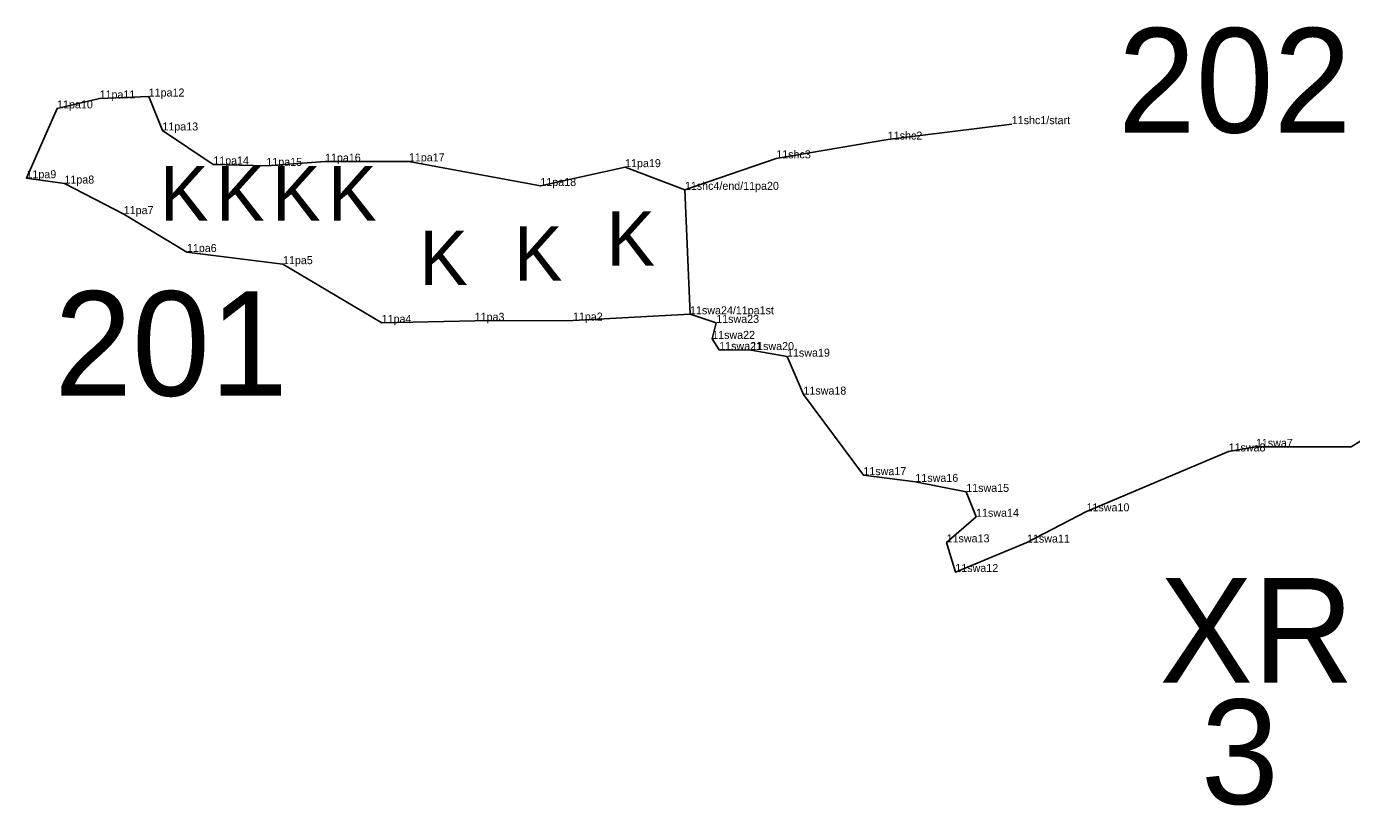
# Model space of a CAD drawing. Extents: x 2072529 to 2268812, y 436423 to 470008.
# Drawn here: x 2225567 to 2226395, y 447962 to 448449 of the extents above; entities that cross this region are included whole.
import ezdxf

# ---------------------------------------------------------------- set-up
doc = ezdxf.new("R2010")
doc.units = 0
for name, color, linetype in [('Old_Level_10', 7, 'Continuous'), ('Old_Level_20', 7, 'Continuous'), ('Old_Level_52', 7, 'Continuous'), ('Old_Level_55', 7, 'Continuous'), ('Old_Level_60', 7, 'Continuous'), ('Old_Level_62', 7, 'Continuous')]:
    doc.layers.add(name, color=color, linetype=linetype)

msp = doc.modelspace()

# ---------------------------------------------------------------- linework, layer by layer
at = {"layer": 'Old_Level_10'}
for points in [[(2225978.686, 448347.107), (2225981.906, 448269.333), (2225998.274, 448263.943), (2225995.753, 448253.963), (2226000.1, 448247.034), (2226020.097, 448246.98), (2226042.5, 448242.86), (2226052.746, 448219.139), (2226090.193, 448168.806), (2226122.677, 448164.597), (2226154.431, 448158.364), (2226160.56, 448142.804), (2226142.212, 448126.808), (2226147.631, 448108.287), (2226192.389, 448126.682), (2226229.566, 448146.2), (2226318.313, 448183.633), (2226335.372, 448186.476), (2226394.83, 448186.41), (2226419.056, 448201.541), (2226431.769, 448228.893), (2226430.927, 448298.983), (2226428.561, 448370.704), (2226419.335, 448414.909)], [(2226182.883, 448388.146), (2226105.414, 448378.517), (2226035.771, 448366.771), (2225978.686, 448347.107)]]:
    msp.add_lwpolyline(points, dxfattribs=at)
at = {"layer": 'Old_Level_20'}
for p, q in [((2225613.084, 448404.204), (2225613.084, 448404.204)), ((2225643.785, 448405.432), (2225643.785, 448405.432)), ((2225586.578, 448397.996), (2225586.578, 448397.996)), ((2226182.883, 448388.146), (2226182.883, 448388.146)), ((2225652.344, 448384.211), (2225652.344, 448384.211)), ((2226105.414, 448378.517), (2226105.414, 448378.517)), ((2225684.091, 448362.94), (2225684.091, 448362.94)), ((2225717.271, 448362.064), (2225717.271, 448362.064)), ((2225753.909, 448364.724), (2225753.909, 448364.724)), ((2225806.3, 448364.892), (2225806.3, 448364.892)), ((2225941.348, 448361.277), (2225941.348, 448361.277)), ((2226035.771, 448366.771), (2226035.771, 448366.771)), ((2225567.454, 448354.369), (2225567.454, 448354.369)), ((2225591.155, 448351.028), (2225591.155, 448351.028)), ((2225888.445, 448349.505), (2225888.445, 448349.505)), ((2225978.686, 448347.107), (2225978.686, 448347.107)), ((2225978.686, 448347.107), (2225978.686, 448347.107)), ((2225628.197, 448331.934), (2225628.197, 448331.934)), ((2225667.64, 448308.251), (2225667.64, 448308.251)), ((2225727.663, 448300.661), (2225727.663, 448300.661)), ((2225789.301, 448263.995), (2225789.301, 448263.995)), ((2225847.392, 448265.261), (2225847.392, 448265.261)), ((2225908.771, 448265.412), (2225908.771, 448265.412)), ((2225908.771, 448265.412), (2225908.771, 448265.412)), ((2225981.906, 448269.333), (2225981.906, 448269.333)), ((2225981.906, 448269.333), (2225981.906, 448269.333)), ((2225998.274, 448263.943), (2225998.274, 448263.943)), ((2225995.753, 448253.963), (2225995.753, 448253.963)), ((2226000.1, 448247.034), (2226000.1, 448247.034)), ((2226020.097, 448246.98), (2226020.097, 448246.98)), ((2226042.5, 448242.86), (2226042.5, 448242.86)), ((2226052.746, 448219.139), (2226052.746, 448219.139)), ((2226318.313, 448183.633), (2226318.313, 448183.633)), ((2226335.372, 448186.476), (2226335.372, 448186.476)), ((2226394.83, 448186.41), (2226394.83, 448186.41)), ((2226090.193, 448168.806), (2226090.193, 448168.806)), ((2226122.677, 448164.597), (2226122.677, 448164.597)), ((2226154.431, 448158.364), (2226154.431, 448158.364)), ((2226229.566, 448146.2), (2226229.566, 448146.2)), ((2226160.56, 448142.804), (2226160.56, 448142.804)), ((2226142.212, 448126.808), (2226142.212, 448126.808)), ((2226192.389, 448126.682), (2226192.389, 448126.682)), ((2226147.631, 448108.287), (2226147.631, 448108.287))]:
    msp.add_line(p, q, dxfattribs=at)
at = {"layer": 'Old_Level_52'}
msp.add_lwpolyline([(2225981.906, 448269.333), (2225908.771, 448265.412), (2225847.392, 448265.261), (2225789.301, 448263.995), (2225727.663, 448300.661), (2225667.64, 448308.251), (2225628.197, 448331.934), (2225591.155, 448351.028), (2225567.454, 448354.369), (2225586.578, 448397.996), (2225613.084, 448404.204), (2225643.785, 448405.432), (2225652.344, 448384.211), (2225684.091, 448362.94), (2225717.271, 448362.064), (2225753.909, 448364.724), (2225806.3, 448364.892), (2225888.445, 448349.505), (2225941.348, 448361.277), (2225978.686, 448347.107)], dxfattribs=at)

# ---------------------------------------------------------------- texts
at = {"layer": 'Old_Level_55'}
for p in [(2225650.802, 448327.945), (2225685.802, 448327.945), (2225720.802, 448327.945), (2225755.802, 448327.945), (2225929.75, 448299.657), (2225812.834, 448287.562), (2225871.964, 448290.25)]:
    msp.add_text('K', height=34, dxfattribs=at).set_placement(p)
at = {"layer": 'Old_Level_60'}
for s, p in [('11pa12', (2225643.785, 448405.432)), ('11pa10', (2225586.578, 448397.996)), ('11pa11', (2225613.084, 448404.204)), ('11pa13', (2225652.344, 448384.211)), ('11shc1/start', (2226182.883, 448388.146)), ('11shc2', (2226105.414, 448378.517)), ('11pa16', (2225753.909, 448364.724)), ('11pa17', (2225806.3, 448364.892)), ('11shc3', (2226035.771, 448366.771)), ('11pa14', (2225684.091, 448362.94)), ('11pa15', (2225717.271, 448362.064)), ('11pa19', (2225941.348, 448361.277)), ('11pa9', (2225567.454, 448354.369)), ('11pa8', (2225591.155, 448351.028)), ('11pa18', (2225888.445, 448349.505)), ('11shc4/end/11pa20', (2225978.686, 448347.107)), ('11shc4/end/11pa20', (2225978.686, 448347.107)), ('11pa7', (2225628.197, 448331.934)), ('11pa6', (2225667.64, 448308.251)), ('11pa5', (2225727.663, 448300.661)), ('11pa3', (2225847.392, 448265.261)), ('11pa2', (2225908.771, 448265.412)), ('11swa24/11pa1st', (2225981.906, 448269.333)), ('11swa24/11pa1st', (2225981.906, 448269.333)), ('11pa4', (2225789.301, 448263.995)), ('11swa23', (2225998.274, 448263.943)), ('11swa22', (2225995.753, 448253.963)), ('11swa21', (2226000.1, 448247.034)), ('11swa20', (2226020.097, 448246.98)), ('11swa19', (2226042.5, 448242.86)), ('11swa18', (2226052.746, 448219.139)), ('11swa8', (2226318.313, 448183.633)), ('11swa7', (2226335.372, 448186.476)), ('11swa17', (2226090.193, 448168.806)), ('11swa16', (2226122.677, 448164.597)), ('11swa15', (2226154.431, 448158.364)), ('11swa14', (2226160.56, 448142.804)), ('11swa10', (2226229.566, 448146.2)), ('11swa13', (2226142.212, 448126.808)), ('11swa11', (2226192.389, 448126.682)), ('11swa12', (2226147.631, 448108.287))]:
    msp.add_text(s, height=5, dxfattribs=at).set_placement(p)
at = {"layer": 'Old_Level_62'}
for s, p in [('202', (2226249.214, 448382.87)), ('201', (2225584.824, 448218.417)), ('XR', (2226275.187, 448039.206)), ('3', (2226301.075, 447963.297))]:
    msp.add_text(s, height=65.34, dxfattribs=at).set_placement(p)

doc.saveas('drawing.dxf')
